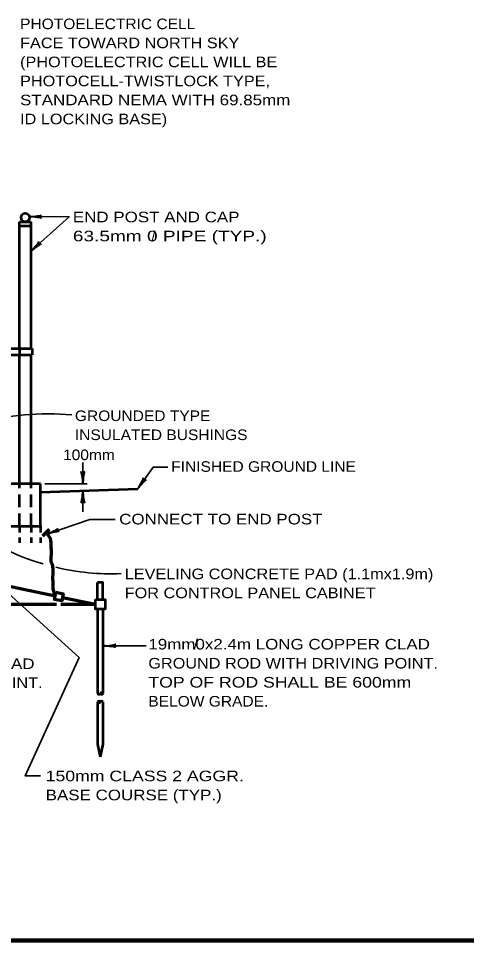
# Model space of a CAD drawing. Extents: x -30 to 826, y -11 to 533.
# Drawn here: x 314.5 to 441.8, y 0.9 to 262.7 of the extents above; entities that cross this region are included whole.
import ezdxf
from ezdxf.enums import TextEntityAlignment as Align

# ---------------------------------------------------------------- set-up
doc = ezdxf.new("R2010")
doc.units = 0
doc.header["$LTSCALE"] = 1.2
doc.linetypes.add('MEDIUM_DASHED', pattern=[4.5, 3, -1.5])
doc.linetypes.add('SHORT_DASHED', pattern=[2.7, 1.5, -1.2])
doc.layers.add('1', color=7, linetype='Continuous', lineweight=53)

msp = doc.modelspace()

# ---------------------------------------------------------------- linework, layer by layer
at = {"layer": '1'}
for p, q in [((314.819, 205.029), (318.119, 205.029)), ((314.819, 169.029), (314.819, 205.029)), ((318.119, 169.029), (318.119, 205.029)), ((314.819, 203.829), (318.119, 203.829)), ((251.936, 169.029), (318.419, 169.029)), ((314.819, 168.729), (314.819, 167.529)), ((318.419, 169.029), (318.419, 167.229)), ((251.936, 167.229), (318.419, 167.229)), ((314.819, 130.629), (314.819, 167.229)), ((318.119, 130.629), (318.119, 167.229)), ((320.819, 118.629), (320.819, 130.629)), ((320.819, 128.229), (348.402, 129.192)), ((291.836, 118.629), (320.819, 118.629)), ((337.019, 97.779), (337.019, 102.579)), ((337.019, 95.079), (337.019, 71.079)), ((338.519, 95.079), (338.519, 71.079)), ((337.019, 68.679), (337.019, 56.679)), ((338.519, 68.679), (338.519, 56.679)), ((337.019, 56.679), (337.769, 53.079)), ((338.519, 56.679), (337.769, 53.079))]:
    msp.add_line(p, q, dxfattribs=at)
at = {"layer": '1', "lineweight": 35}
for p, q in [((332.819, 130.629), (332.819, 136.629)), ((322.019, 130.629), (334.019, 130.629)), ((332.819, 128.69), (332.819, 122.69)), ((338.74, 84.615), (350.764, 84.615))]:
    msp.add_line(p, q, dxfattribs=at)
at = {"layer": '1', "linetype": 'MEDIUM_DASHED'}
for p, q in [((314.819, 118.629), (314.819, 130.629)), ((318.119, 118.629), (318.119, 130.629))]:
    msp.add_line(p, q, dxfattribs=at)
at = {"layer": '1', "linetype": 'SHORT_DASHED'}
for p, q in [((314.819, 118.629), (314.819, 113.829)), ((318.119, 118.629), (318.119, 113.829)), ((320.819, 118.629), (320.819, 113.829))]:
    msp.add_line(p, q, dxfattribs=at)
at = {"layer": '1', "lineweight": 70}
for p, q in [((323.269, 117.683), (321.373, 115.754)), ((307.319, 102.48), (324.964, 98.811)), ((327.02, 98.383), (336.419, 96.429)), ((307.319, 96.429), (325.319, 96.429)), ((326.519, 96.429), (336.419, 96.429))]:
    msp.add_line(p, q, dxfattribs=at)
at = {"layer": '1', "lineweight": 158}
msp.add_line((819.196, 0.944), (27.596, 0.944), dxfattribs=at)
at = {"layer": '1', "lineweight": 35}
for points in [[(317.639, 206.497), (328.909, 206.446), (318.119, 196.762)], [(348.402, 129.192), (352.773, 135.323), (357.012, 135.323)], [(322.635, 116.366), (334.849, 120.531), (342.015, 120.531)], [(295.374, 114.118), (331.752, 81.326), (316.441, 47.711), (320.757, 47.711)]]:
    msp.add_lwpolyline(points, dxfattribs=at)
at = {"layer": '1'}
for points in [[(320.819, 130.629), (294.419, 130.629), (294.419, 131.829), (232.019, 131.829), (232.019, 130.629), (227.819, 130.629), (227.819, 131.829), (166.619, 131.829), (166.619, 130.629)], [(338.519, 97.779), (338.519, 102.579), (337.019, 102.579)]]:
    msp.add_lwpolyline(points, dxfattribs=at)
at = {"layer": '1', "lineweight": 70}
msp.add_lwpolyline([(325.178, 99.839), (327.234, 99.412), (326.806, 97.355), (324.75, 97.783)], close=True, dxfattribs=at)
at = {"layer": '1'}
msp.add_lwpolyline([(336.419, 97.779), (339.119, 97.779), (339.119, 95.079), (336.419, 95.079)], close=True, dxfattribs=at)
msp.add_circle((316.469, 206.229), 1.2, dxfattribs=at)
at = {"layer": '1', "lineweight": 35}
for centre, radius, start, end in [((322.958, 81.674), 68.847, 84.36386, 129.06474), ((340.984, 174.124), 69.056, 219.03891, 253.64268), ((340.984, 174.124), 69.056, 256.72245, 272.24824)]:
    msp.add_arc(centre, radius, start, end, dxfattribs=at)
at = {"layer": '1'}
for centre, start, end in [((337.394, 71.295), 209.9406, 330.0594), ((338.144, 70.863), 29.9406, 150.0594), ((338.144, 71.295), 209.9406, 330.0594), ((337.394, 68.463), 29.9406, 150.0594), ((337.394, 68.895), 209.9406, 330.0594), ((338.144, 68.463), 29.9406, 150.0594)]:
    msp.add_arc(centre, 0.433, start, end, dxfattribs=at)
at = {"layer": '1', "lineweight": 40}
for centre, major_axis, ratio, start_param, end_param in [((318.95, 206.822), (-2.144, -0.178), 0.122415, 0.8963533, 3.1415927), ((318.95, 206.822), (-2.144, -0.178), 0.122415, 0.8963533, 3.1415927), ((318.982, 206.237), (-2.107, 0.22), 0.07063, 3.1407148, 5.41811), ((318.982, 206.237), (-2.107, 0.22), 0.07063, 3.1407148, 5.41811), ((318.872, 197.884), (-1.47, -1.571), 0.122415, 0.8963533, 3.1415927), ((318.872, 197.884), (-1.47, -1.571), 0.122415, 0.8963533, 3.1415927), ((319.289, 197.471), (1.709, 1.251), 0.07063, 6.2823074, 8.5597026), ((319.289, 197.471), (1.709, 1.251), 0.07063, 6.2823074, 8.5597026), ((332.488, 131.939), (0.187, -2.143), 0.122415, 0.8963533, 3.1415927), ((332.488, 131.939), (0.187, -2.143), 0.122415, 0.8963533, 3.1415927), ((333.073, 131.974), (-0.211, -2.108), 0.07063, 3.1407148, 5.41811), ((333.073, 131.974), (-0.211, -2.108), 0.07063, 3.1407148, 5.41811), ((348.892, 130.451), (-1.091, -1.854), 0.122415, 0.8963533, 3.1415927), ((349.39, 130.14), (-1.395, -1.594), 0.07063, 3.1407148, 5.41811), ((332.565, 127.345), (0.211, 2.108), 0.07063, 3.1407148, 5.41811), ((332.565, 127.345), (0.211, 2.108), 0.07063, 3.1407148, 5.41811), ((333.151, 127.381), (-0.187, 2.143), 0.122415, 0.8963533, 3.1415927), ((333.151, 127.381), (-0.187, 2.143), 0.122415, 0.8963533, 3.1415927), ((323.767, 117.102), (-1.968, -0.869), 0.122415, 0.8963533, 3.1415927), ((323.767, 117.102), (-1.968, -0.869), 0.122415, 0.8963533, 3.1415927), ((323.989, 116.56), (-2.063, -0.481), 0.07063, 3.1407148, 5.41811), ((323.989, 116.56), (-2.063, -0.481), 0.07063, 3.1407148, 5.41811), ((340.085, 84.361), (-2.108, 0.211), 0.07063, 3.1407148, 5.41811), ((340.085, 84.361), (-2.108, 0.211), 0.07063, 3.1407148, 5.41811), ((340.05, 84.947), (-2.143, -0.187), 0.122415, 0.8963533, 3.1415927), ((340.05, 84.947), (-2.143, -0.187), 0.122415, 0.8963533, 3.1415927)]:
    msp.add_ellipse(centre, major_axis=major_axis, ratio=ratio, start_param=start_param, end_param=end_param, dxfattribs=at)
at = {"layer": '1', "lineweight": 70}
msp.add_spline([(324.964, 98.811), (324.38, 101.5), (324.413, 102.546), (324.315, 103.691), (324.38, 105.096), (324.413, 106.339), (324.151, 107.614), (323.89, 108.366), (323.825, 109.641), (323.923, 111.34), (323.825, 112.615), (323.596, 115.067), (322.387, 116.702)], degree=3, dxfattribs=at)

# ---------------------------------------------------------------- texts
at = {"layer": '1'}
for s, width, p in [('PHOTOELECTRIC CELL', 1.1, (314.992, 259.704)), ('FACE TOWARD NORTH SKY', 1.15, (314.992, 254.304)), ('(PHOTOELECTRIC CELL WILL BE', 1.15, (314.992, 248.904)), ('PHOTOCELL-TWISTLOCK TYPE,', 1.15, (314.992, 243.504)), ('STANDARD NEMA WITH 69.85mm', 1.2, (314.992, 238.104)), ('ID LOCKING BASE)', 1.15, (314.992, 232.704)), ('END POST AND CAP', 1.2, (329.981, 204.877)), ('63.5mm 0 PIPE (TYP.)', 1.35, (329.981, 199.477)), ('GROUNDED TYPE', 1.1, (330.561, 148.443)), ('INSULATED BUSHINGS', 1.1, (330.561, 143.043)), ('100mm', 1.1, (327.188, 137.353)), ('FINISHED GROUND LINE', 1.1, (357.921, 134.027)), ('CONNECT TO END POST', 1.2, (343.144, 119.099)), ('LEVELING CONCRETE PAD (1.1mx1.9m)', 1.15, (344.719, 103.548)), ('FOR CONTROL PANEL CABINET', 1.15, (344.719, 98.148)), ('19mm0x2.4m LONG COPPER CLAD', 1.2, (351.43, 83.581)), ('GROUND ROD WITH DRIVING POINT.', 1.15, (351.43, 78.181)), ('19mm0x2.4m LONG COPPER CLAD', 1.2, (239.117, 78.035)), ('GROUND ROD WITH DRIVING POINT.', 1.15, (239.117, 72.635)), ('TOP OF ROD SHALL BE 600mm', 1.25, (351.43, 72.781)), ('BELOW GRADE.', 1.1, (351.43, 67.381)), ('150mm CLASS 2 AGGR.', 1.25, (322.259, 46.173)), ('BASE COURSE (TYP.)', 1.2, (322.259, 40.773))]:
    msp.add_text(s, height=3, dxfattribs=dict(at, width=width)).set_placement(p)
msp.add_text('/', height=3, dxfattribs=at).set_placement((352.315, 199.389))
msp.add_text('/', height=3, dxfattribs=at).set_placement((364.914, 83.615), align=Align.CENTER)

doc.saveas('drawing.dxf')
